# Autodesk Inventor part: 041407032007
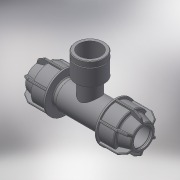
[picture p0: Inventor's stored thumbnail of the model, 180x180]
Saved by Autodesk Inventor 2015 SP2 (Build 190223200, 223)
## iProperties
Created: 2017-08
Part Number: 041407032007
Material: Generic
Description: PLASSON IRRIFIT TEE FEMALE ADAPTOR 32-3/4"-32
Document SubType Name: Modeling
Designer: KIM
Density: 1 g/cm^3
Appearance: Default
Author: KIM
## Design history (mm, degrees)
derived "041407.ipt"
feature "Solid1::041407.ipt"
feature "Solid2::041407.ipt"
tag "TaggingFeature1"
body "Solid1"
other parameters: "d1" = 32, "d2" = 38, "d4" = 15 deg, "d5" = 36.1, "d6" = 14.44, "d10" = 57, "d16" = 32.64, "d17" = 1.9, "d22" = 41.6, "d24" = 1.9, "d25" = 51.3, "d26" = 42.75, "d27" = 1.9, "d28" = 135 deg, "d29" = 1.14, "d31" = 1.6, "d46" = 150 deg, "d49" = 2.85, "d50" = 0, "d58" = 0.96, "d61" = 360 deg, "d63" = 28.8, "d64" = 64.5, "d80" = 45.76, "d81" = 0.32, "d94" = 55, "d96" = 24.2203, "d108" = 0.96, "d113" = 13.0417, "d115" = 20.4, "d117" = 16.7679, "d118" = 3.8, "d119" = 17, "d120" = 18.631, "d121" = 0.37262, "d122" = 5.1, "d123" = 3.8, "d128" = 24.2203, "d130" = 0, "d132" = 0, "d_" = 32, "G_" = 18.631, "E_" = 57, "H_" = 129, "l_" = 38, "l_1" = 17, "A_" = 55
